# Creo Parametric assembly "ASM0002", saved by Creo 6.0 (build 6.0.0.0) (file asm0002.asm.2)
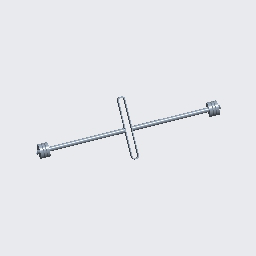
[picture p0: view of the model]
Units: millimeter Newton Second (mmNs); MM, TONNE, SECS

Created from: MMNS_ASM_DESIGN.ASM

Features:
  1. datum plane "ASM_RIGHT"
  2. datum plane "ASM_TOP"
  3. datum plane "ASM_FRONT"
  4. coordinate system
  5. component "YOKE"
  6. component "PISTON"
  7. component "PISTON"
